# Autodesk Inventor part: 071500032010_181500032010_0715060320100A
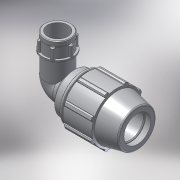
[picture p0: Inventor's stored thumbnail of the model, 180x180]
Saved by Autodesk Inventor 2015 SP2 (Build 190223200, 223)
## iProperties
Created: 2017-02
Part Number: 071500032010_181500032010_0715060320100A
Material: PVC-Piping
Description: PLASSON 90° ELBOW FEMALE ADAPTOR 32-1"
Document SubType Name: Modeling
Designer: KIM
Mass: 92.6774 g
Surface Area: 199.44 cm^2
Volume: 66.1981 cm^3
Density: 1.4 g/cm^3
Appearance: Smooth - White
Author: KIM
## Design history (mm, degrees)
derived "07150.ipt"
feature "Solid1::07150.ipt"
tag "TaggingFeature1"
body "Solid1"
other parameters: "d2" = 32, "d4" = 7.91667, "d5" = 23.75, "d7" = 64, "d9" = 13.57143, "d11" = 3.16667, "d13" = 120 deg, "d14" = 44.8, "d15" = 12 deg, "d16" = 55.68, "d18" = 1.6, "d19" = 35 deg, "d20" = 17.5 deg, "d21" = 59.52, "d23" = 0, "d25" = 360 deg, "d27" = 1.28, "d33" = 0.64, "d42" = 35.15, "d43" = 1.92, "d46" = 0.96, "d51" = 95, "d68" = 3.16667, "d72" = 54, "d73" = 39.3783, "d74" = 21, "d75" = 45.28505, "d76" = 30.291, "d77" = 23.1, "d79" = 12.1164, "d80" = 0.90873, "d83" = 0, "d84" = 0, "d91" = 48, "d93" = 67, "d94" = 30.291, "d95" = 21.2037, "d96" = 9.5, "d97" = 50 deg, "d98" = 27.2619, "d99" = 0.5, "d100" = 0.5, "d101" = 7, "d102" = 39.3783, "d103" = 17.85, "d104" = 0, "d108" = 360 deg, "d110" = 1.18135, "d_" = 32, "E_" = 64, "A_" = 95, "l_" = 67, "l_2" = 21, "A_1" = 54, "Rp_" = 30.291, "d105" = 5.90674
